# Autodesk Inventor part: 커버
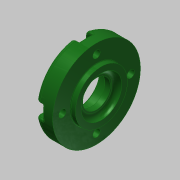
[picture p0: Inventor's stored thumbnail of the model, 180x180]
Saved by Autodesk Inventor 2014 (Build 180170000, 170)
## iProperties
Created: 2015-11
Part Number: 커버
Material: 알루미늄 6061
Document SubType Name: Modeling
Designer: mduedu
Density: 1 g/cm^3
Appearance: Smooth - Dark Forest Green
Author: mduedu
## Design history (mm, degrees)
sketch "스케치1"
  geometry: L1 (-7, 0)-(7, 0); L2 (-7, 0)-(-7, 27); L3 (-7, 27)-(4, 27); L4 (4, 27)-(4, 16); L5 (4, 16)-(7, 16); L6 (7, 16)-(7, 0); 2 further points
  constraints: 12 end point, 3 perpendicular, 2 parallel, 1 coincident, 1 horizontal, 1 midpoint
  dimensions: "d0" = 14 distance of L1.start L1.end; "d1" = 54 diameter of L3 L1; "d2" = 3 distance of L4.end L5.end; "d3" = 32 diameter of L5 L1
revolve "회전1" sketch "스케치1" stored, may be unused: angle "d4" = 90 deg
hole "구멍1" diameter "d7" = 25; stored, may be unused: countersink angle "d11" = 90 deg, drill point angle "d13" = 0 deg; dims "d5" = 10, "d6" = 10, "d8" = 6, "d9" = 4, "d10" = 2, "d12" = 3
hole "구멍2" diameter "d16" = 25; stored, may be unused: countersink angle "d20" = 90 deg, drill point angle "d22" = 0 deg; dims "d17" = 6, "d18" = 4, "d19" = 2, "d21" = 7.7, "d58" = 10, "d59" = 10
hole "구멍3" diameter "d25" = 17; stored, may be unused: countersink angle "d29" = 90 deg, drill point angle "d31" = 0 deg; dims "d23" = 10, "d24" = 10, "d26" = 6, "d27" = 4, "d28" = 2, "d30" = 4.2
chamfer "모따기1" distance "d32" = 0.6; stored, may be unused: second distance "d33" = 2, angle "d34" = 30 deg
fillet "모깎기1" dims "d35" = 0.3
fillet "모깎기2" dims "d36" = 3
fillet "모깎기3" dims "d37" = 3
fillet "모깎기4" dims "d38" = 0.3
sketch "스케치3" dims "d61" = 42
  geometry: C1 r 27 at (0, 0) reference; 2 further points
  constraints: 2 vertical alignment, 1 coincident, 2 other
hole "구멍4" sketch "스케치3" at (0, 21) diameter "d44" = 4.5; stored, may be unused: countersink angle "d48" = 90 deg, drill point angle "d50" = 0 deg; dims "d45" = 6, "d46" = 8, "d47" = 4.6, "d49" = 8
sketch "스케치4"
  geometry: L1 (-4, 5.702)-(-4, 0); L2 (4, 5.702)-(4, 0); A1 r 27 centre (0, -21) between (-4, 5.702) and (4, 5.702) reference; A2 r 4 centre (0, 0) between (-2.824, 2.833) and (2.824, 2.833) reference
  constraints: 4 end point, 4 point on circle, 2 tangent, 2 vertical
extrude "돌출1" cut sketch "스케치4" stored distance "d51" = 0; taper "d52" = 0 deg
fillet "모깎기5" dims "d56" = 0.3
fillet "모깎기6" dims "d57" = 1
node "솔리드1"
pattern_circular "원형 패턴2" dims angle "d64" = 360 deg
pattern_circular "원형 패턴1" dims angle "d54" = 360 deg
